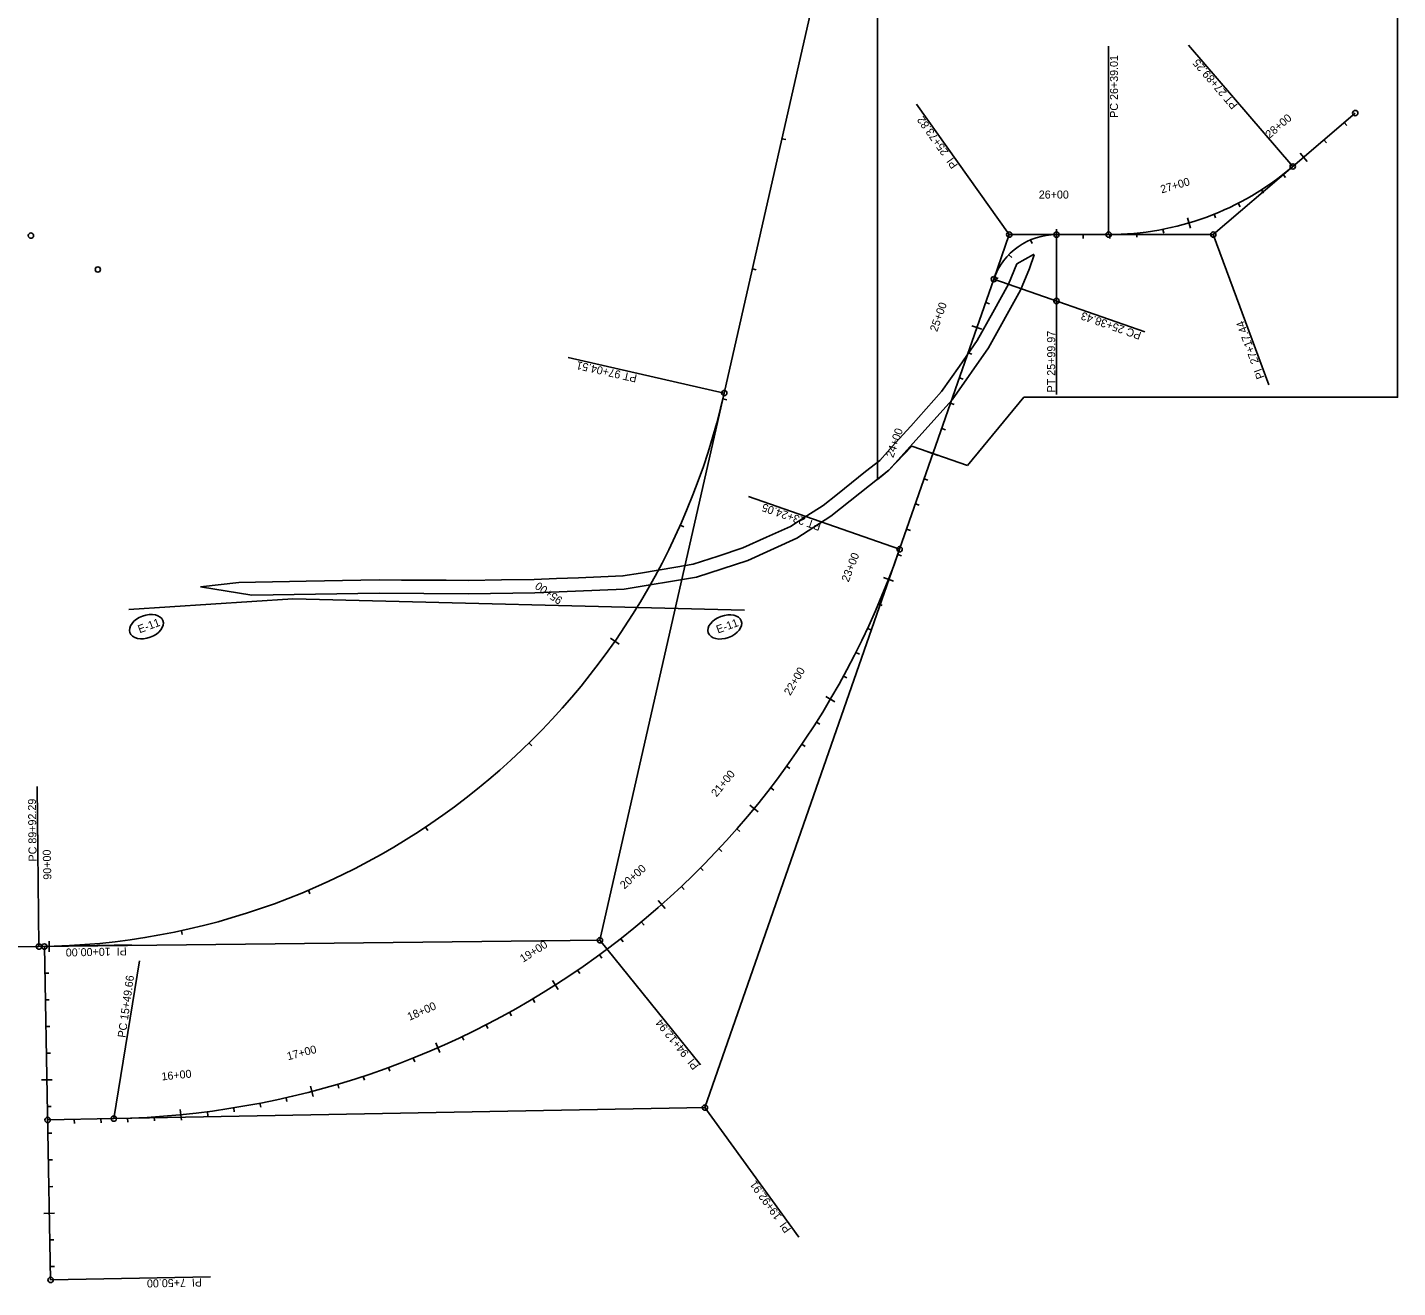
# Model space of a CAD drawing. Extents: x 1710760 to 1713003, y 548603 to 551142.
# Drawn here: x 1711724 to 1712752, y 548957 to 549901 of the extents above; entities that cross this region are included whole.
import ezdxf

# ---------------------------------------------------------------- set-up
doc = ezdxf.new("R2010")
doc.units = 0
for name, color, linetype in [('R_Contours', 7, 'Continuous'), ('R_MOT', 7, 'Continuous'), ('R_No Plot', 7, 'Continuous'), ('R_Point Sym', 7, 'Continuous'), ('R_Proposed Road_Shoulder', 7, 'Continuous')]:
    doc.layers.add(name, color=color, linetype=linetype)

msp = doc.modelspace()

# ---------------------------------------------------------------- linework, layer by layer
at = {"layer": 'R_Contours'}
for p, q in [((1712613.4, 549746.1), (1712673, 549797.1)), ((1712448.9, 549712.7), (1712460.5, 549746.1)), ((1712460.5, 549746.1), (1712495.9, 549746.1)), ((1712535, 549746.1), (1712613.4, 549746.1)), ((1712153.6, 549217.1), (1712246.8, 549627.3)), ((1712232.3, 549091.7), (1712378.3, 549510.2)), ((1711733, 549212.4), (1712153.6, 549217.1)), ((1711737.1, 549212.4), (1711802.4, 549213.6)), ((1711789.2, 549083.4), (1712232.3, 549091.7))]:
    msp.add_line(p, q, dxfattribs=at)
for points in [[(1712535, 549746.1), (1712535, 549887.4)], [(1712673, 549797.1), (1712594.9, 549888.2)], [(1712460.5, 549746.1), (1712391, 549843.9)], [(1712713.5, 549827.8), (1712711.5, 549830.1)], [(1712293, 549817.3), (1712290.1, 549817.9)], [(1712698.3, 549814.8), (1712696.3, 549817.1)], [(1712678.5, 549807.1), (1712683.7, 549801)], [(1712667.7, 549788.8), (1712665.8, 549791.2)], [(1712651.1, 549777.1), (1712649.5, 549779.6)], [(1712633.6, 549767), (1712632.2, 549769.7)], [(1712594, 549758.6), (1712596.3, 549750.9)], [(1712615.1, 549758.6), (1712614, 549761.3)], [(1712496, 549750.1), (1712496, 549742.1)], [(1712576.3, 549747.1), (1712575.7, 549750)], [(1712477.7, 549739.4), (1712476.5, 549742.1)], [(1712495.9, 549746.1), (1712495.9, 549626.1)], [(1712516, 549743.1), (1712516, 549746.1)], [(1712536, 549743.1), (1712536, 549746.1)], [(1712556.2, 549744.1), (1712555.9, 549747.1)], [(1712613.4, 549746.1), (1712655, 549633.5)], [(1712462.3, 549728.8), (1712460.1, 549730.9)], [(1712270.8, 549719.7), (1712267.9, 549720.4)], [(1712448.9, 549712.7), (1712562.2, 549673.1)], [(1712452.2, 549713.1), (1712449.4, 549714.1)], [(1712445.6, 549694.3), (1712442.8, 549695.3)], [(1712432.4, 549677.7), (1712440, 549675.1)], [(1712432.5, 549656.5), (1712429.6, 549657.5)], [(1712246.8, 549627.3), (1712129.8, 549653.9)], [(1712425.9, 549637.6), (1712423.1, 549638.6)], [(1712248.7, 549622.2), (1712245.8, 549622.9)], [(1712419.3, 549618.7), (1712416.5, 549619.7)], [(1712412.7, 549599.8), (1712409.9, 549600.8)], [(1712399.5, 549583.3), (1712407.1, 549580.6)], [(1712399.5, 549562.1), (1712396.7, 549563.1)], [(1712378.3, 549510.2), (1712265, 549549.8)], [(1712393, 549543.2), (1712390.1, 549544.2)], [(1712216.6, 549527.1), (1712213.8, 549528.3)], [(1712386.4, 549524.3), (1712383.5, 549525.3)], [(1712379.8, 549505.4), (1712376.9, 549506.4)], [(1712366.2, 549489.1), (1712373.7, 549486.2)], [(1712365.1, 549468), (1712362.4, 549469.2)], [(1712356.9, 549449.7), (1712354.2, 549450.9)], [(1712161.5, 549443.6), (1712168.1, 549439)], [(1712348.1, 549431.6), (1712345.5, 549432.9)], [(1712338.8, 549413.8), (1712336.2, 549415.2)], [(1712322.9, 549399.8), (1712329.8, 549395.8)], [(1712318.5, 549379.1), (1712315.9, 549380.7)], [(1712102.5, 549362.8), (1712100.4, 549365)], [(1712307.5, 549362.3), (1712305, 549364)], [(1712296, 549345.8), (1712293.6, 549347.6)], [(1711733, 549212.4), (1711731.7, 549332.3)], [(1712284, 549329.7), (1712281.6, 549331.5)], [(1712266.1, 549318.4), (1712272.3, 549313.3)], [(1712024.6, 549299.5), (1712022.9, 549302)], [(1712258.5, 549298.6), (1712256.2, 549300.6)], [(1712245, 549283.7), (1712242.8, 549285.8)], [(1712231.1, 549269.3), (1712229, 549271.4)], [(1711936.2, 549251.8), (1711935, 549254.6)], [(1712216.7, 549255.2), (1712214.7, 549257.4)], [(1712197.3, 549246.9), (1712202.6, 549240.9)], [(1711840.5, 549221.5), (1711839.8, 549224.4)], [(1712186.7, 549228.5), (1712184.8, 549230.8)], [(1711740.6, 549216.5), (1711740.8, 549208.5)], [(1712153.6, 549217.1), (1712229, 549123.7)], [(1712171, 549215.9), (1712169.2, 549218.3)], [(1712155, 549203.8), (1712153.2, 549206.2)], [(1711789.2, 549083.4), (1711808.5, 549201.7)], [(1712138.6, 549192.2), (1712136.9, 549194.7)], [(1711740.4, 549192.5), (1711737.4, 549192.4)], [(1712118.1, 549187), (1712122.4, 549180.2)], [(1711740.8, 549172.5), (1711737.8, 549172.4)], [(1712104.8, 549170.5), (1712103.2, 549173.1)], [(1712087.4, 549160.5), (1712085.9, 549163.1)], [(1711741.2, 549152.5), (1711738.2, 549152.4)], [(1712069.6, 549151), (1712068.3, 549153.7)], [(1712051.6, 549142.1), (1712050.3, 549144.8)], [(1711741.6, 549132.5), (1711738.6, 549132.4)], [(1712030.5, 549140.2), (1712033.7, 549132.9)], [(1711996, 549118.9), (1711995, 549121.7)], [(1712014.8, 549126), (1712013.7, 549128.8)], [(1711734.9, 549112.4), (1711742.9, 549112.5)], [(1711977, 549112.3), (1711976.1, 549115.1)], [(1711936.7, 549107.7), (1711938.7, 549100)], [(1711957.9, 549106.3), (1711957, 549109.2)], [(1711742.3, 549092.5), (1711739.3, 549092.4)], [(1711839, 549090.3), (1711839.8, 549082.3)], [(1711879.5, 549088.5), (1711879.1, 549091.5)], [(1711899.3, 549092), (1711898.7, 549095)], [(1711919, 549096.2), (1711918.3, 549099.1)], [(1712232.3, 549091.7), (1712302.7, 548994.5)], [(1711759.6, 549079.8), (1711759.5, 549082.8)], [(1711779.6, 549080.2), (1711779.5, 549083.2)], [(1711799.6, 549080.7), (1711799.5, 549083.7)], [(1711819.7, 549081.7), (1711819.5, 549084.7)], [(1711859.7, 549085.6), (1711859.3, 549088.6)], [(1711742.7, 549072.5), (1711739.7, 549072.4)], [(1711743.1, 549052.5), (1711740.1, 549052.4)], [(1711743.4, 549032.5), (1711740.4, 549032.4)], [(1711736.8, 549012.4), (1711744.8, 549012.5)], [(1711744.2, 548992.5), (1711741.2, 548992.5)], [(1711744.6, 548972.5), (1711741.6, 548972.5)], [(1711741.8, 548962.5), (1711861.7, 548964.7)]]:
    msp.add_lwpolyline(points, dxfattribs=at)
for centre in [(1712719.9, 549837.2), (1712673, 549797.1), (1712460.5, 549746.1), (1712495.9, 549746.1), (1712535, 549746.1), (1712613.4, 549746.1), (1711727, 549745.3), (1711777.2, 549719.9), (1712448.9, 549712.7), (1712495.9, 549696.3), (1712246.8, 549627.3), (1712378.3, 549510.2), (1711733, 549212.4), (1711733, 549212.4), (1711737.1, 549212.4), (1712153.6, 549217.1), (1712232.3, 549091.7), (1711739.5, 549082.4), (1711789.2, 549083.4), (1711741.8, 548962.5)]:
    msp.add_circle(centre, 2, dxfattribs=at)
at = {"layer": 'R_MOT'}
for points in [[(1712479.2, 549730.9), (1712475.6, 549720.7), (1712469, 549704.5), (1712444.8, 549661.3), (1712417.6, 549622.2), (1712370.3, 549569.5), (1712326.8, 549535), (1712301.3, 549518.4), (1712264.4, 549501.9), (1712226, 549489.2), (1712171.9, 549480.3), (1712104.7, 549477.5), (1712055.1, 549476.9), (1711988.1, 549477.2), (1711892.7, 549475.7), (1711854.2, 549482.1)], [(1712466.2, 549724.2), (1712478.7, 549731.2), (1712479.2, 549730.9)], [(1711854.2, 549482.1), (1711882.9, 549485.3), (1711895.5, 549485.6), (1711908.2, 549485.9), (1711920.8, 549486.1), (1711933.4, 549486.4), (1711947, 549486.6), (1711960.7, 549486.8), (1711974.4, 549487), (1711988, 549487.2), (1712004.8, 549487.1), (1712021.5, 549487.1), (1712038.3, 549487), (1712055, 549486.9), (1712079.7, 549487.2), (1712104.4, 549487.5), (1712121, 549488.2), (1712137.6, 549488.9), (1712154.2, 549489.6), (1712170.8, 549490.2), (1712184, 549492.4), (1712197.2, 549494.6), (1712210.4, 549496.8), (1712223.6, 549499), (1712242.2, 549505.1), (1712260.8, 549511.2), (1712278.6, 549519.2), (1712296.5, 549527.2), (1712308.7, 549535.2), (1712320.9, 549543.1), (1712331.6, 549551.5), (1712342.2, 549560), (1712352.8, 549568.4), (1712363.4, 549576.8), (1712375, 549589.7), (1712386.6, 549602.6), (1712398.2, 549615.5), (1712409.8, 549628.4), (1712423.1, 549647.5), (1712436.3, 549666.6), (1712448.2, 549687.7), (1712460, 549708.8), (1712466.2, 549724.2)]]:
    msp.add_lwpolyline(points, dxfattribs=at)
at = {"layer": 'R_No Plot'}
msp.add_line((1712429.3, 549572.9), (1712471.5, 549624.2), dxfattribs=at)
for points in [[(1712635.8, 549942.6), (1712361.6, 549942.6), (1712361.6, 549562.6)], [(1712471.5, 549624.2), (1712751.6, 549624.2), (1712751.6, 549942.6), (1712636.3, 549942.6)], [(1712361.6, 549562.6), (1712370.3, 549569.5), (1712387.4, 549587.5), (1712429.3, 549572.9)]]:
    msp.add_lwpolyline(points, dxfattribs=at)
at = {"layer": 'R_Point Sym'}
for p, q in [((1712246.8, 549627.3), (1712450.8, 550525.8)), ((1712673, 549797.1), (1712719.9, 549837.2)), ((1712495.9, 549746.1), (1712535, 549746.1)), ((1712378.3, 549510.2), (1712448.9, 549712.7)), ((1711391.8, 549208.5), (1711733, 549212.4)), ((1711741.8, 548962.5), (1711737.1, 549212.4)), ((1711739.5, 549082.4), (1711789.2, 549083.4))]:
    msp.add_line(p, q, dxfattribs=at)
for centre, radius, start, end in [((1712535, 549958.3), 212.2, 270, 310.5648), ((1712495.9, 549696.3), 49.8, 90, 160.7734), ((1711727, 549745.3), 533, 270.6428, 347.2066), ((1711777.2, 549719.9), 636.6, 271.0787, 340.7734)]:
    msp.add_arc(centre, radius, start, end, dxfattribs=at)
at = {"layer": 'R_Proposed Road_Shoulder'}
for p, q in [((1711800.5, 549465), (1711923.3, 549473)), ((1711923.3, 549473), (1712261.9, 549464.5))]:
    msp.add_line(p, q, dxfattribs=at)
for centre in [(1711813.6, 549452.2), (1712247.2, 549452)]:
    msp.add_ellipse(centre, major_axis=(12.4, 4.5), ratio=0.638788, dxfattribs=at)

# ---------------------------------------------------------------- texts
at = {"layer": 'R_Contours'}
for s, rotation, p in [('PC 26+39.01', 90, (1712542, 549833.6)), ('PT 27+89.25', 130.5648, (1712632.1, 549843.3)), ('PI  25+73.82', 125.3867, (1712422.3, 549798.2)), ('28+00', 40.5648, (1712655.7, 549817.9)), ('27+00', 16.4663, (1712574.8, 549776.9)), ('25+00', 70.7734, (1712406.4, 549672.8)), ('PC 25+38.43', 160.7734, (1712560, 549672.8)), ('PI  27+17.44', 110.2824, (1712651.9, 549639.1)), ('PT 25+99.97', 90, (1712494.9, 549627.8)), ('PT 97+04.51', 167.2066, (1712181.8, 549641)), ('24+00', 70.7734, (1712373.5, 549578.4)), ('PT 23+24.05', 160.7734, (1712319.9, 549529.5)), ('23+00', 68.6088, (1712340, 549485.2)), ('95+00', 145.2214, (1712126.2, 549473.3)), ('22+00', 59.6088, (1712296.3, 549400.1)), ('21+00', 50.6088, (1712241, 549324.1)), ('PC 89+92.29', 90.6428, (1711731.3, 549276.2)), ('90+00', 91.4714, (1711742.4, 549262.6)), ('20+00', 41.6088, (1712171.9, 549255.1)), ('19+00', 32.6088, (1712096, 549200.2)), ('PI  10+00.00', 181.0787, (1711798.8, 549211.8)), ('PC 15+49.66', 82.0728, (1711797.9, 549143.8)), ('18+00', 23.6088, (1712010.8, 549156.7)), ('PI  94+12.94', 128.9247, (1712228.2, 549123.1)), ('17+00', 14.6088, (1711919.8, 549127.1)), ('16+00', 5.6088, (1711825.2, 549112)), ('PI  19+92.91', 125.926, (1712297.2, 549000.5)), ('PI  7+50.00', 181.0787, (1711855.2, 548963.6))]:
    msp.add_text(s, height=6, rotation=rotation, dxfattribs=at).set_placement(p)
msp.add_text('26+00', height=6, dxfattribs=at).set_placement((1712482.6, 549773.1))
at = {"layer": 'R_Proposed Road_Shoulder'}
for p in [(1711808.5, 549447.2), (1712242.1, 549447)]:
    msp.add_text('E-11', height=6, rotation=20, dxfattribs=at).set_placement(p)

doc.saveas('drawing.dxf')
